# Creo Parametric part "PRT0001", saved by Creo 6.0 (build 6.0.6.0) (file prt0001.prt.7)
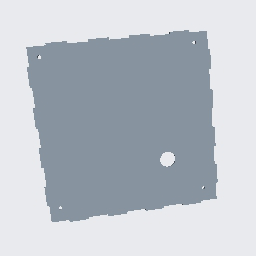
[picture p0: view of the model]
Units: Inch lbm Second (Pro/E Default); INCH, POUND, SECS

Created from: INLBS_PART_SOLID.PRT

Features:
  1. datum plane "RIGHT"
  2. datum plane "TOP"
  3. datum plane "FRONT"
  4. coordinate system
  5. sketch "Sketch 1"
  6. extrusion "Extrude 1"
  7. sketch "Sketch 2"
  8. extruded cut "Extrude 2"
  9. sketch "Sketch 3"
  10. extruded cut "Extrude 3"
  11. sketch "Sketch 4"
  12. extruded cut "Extrude 4"

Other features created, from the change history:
  extrusion "Extrude 2" (2 times)
  mirror "Mirror 1"

Surfaces: 70 plane, 5 cylinder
